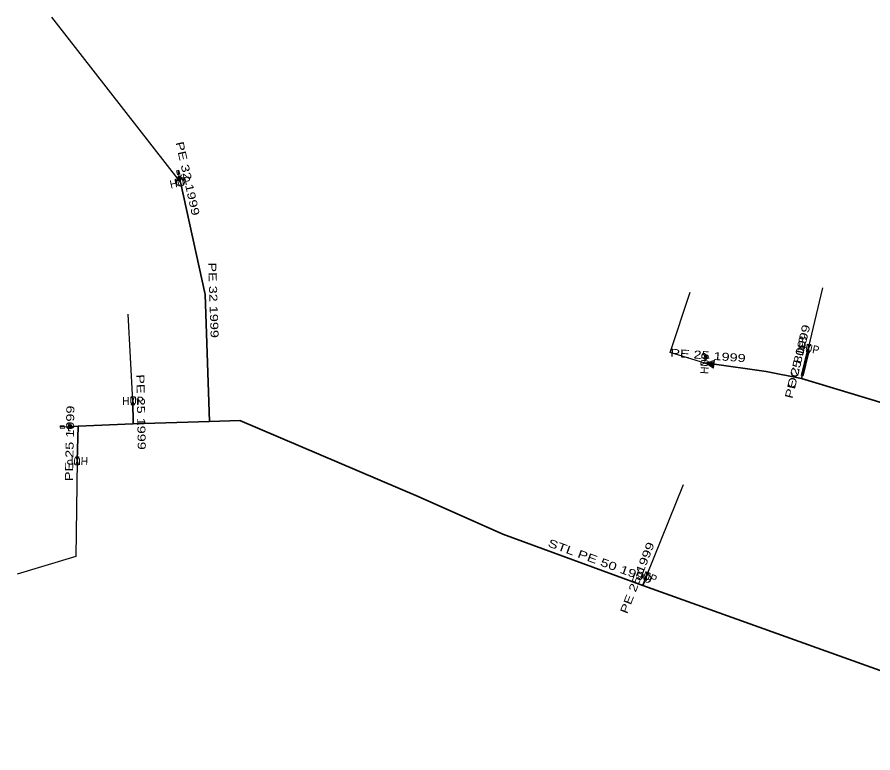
# Model space of a CAD drawing. Extents: x -737484 to -734496, y -1033882 to -1030666.
# Drawn here: x -736088.3 to -735981.3, y -1032114.3 to -1032022.4 of the extents above; entities that cross this region are included whole.
import ezdxf
from ezdxf.enums import TextEntityAlignment as Align

# ---------------------------------------------------------------- set-up
doc = ezdxf.new("R2010")
doc.units = 0
doc.header["$LTSCALE"] = 0.4
for name, color, linetype, lineweight in [('1', 7, 'Continuous', 13), ('18', 7, 'Continuous', 60), ('22', 7, 'Continuous', 25), ('5', 7, 'Continuous', 35), ('7', 7, 'Continuous', 35)]:
    doc.layers.add(name, color=color, linetype=linetype, lineweight=lineweight)
doc.layers.add('2', color=7, linetype='Continuous')

msp = doc.modelspace()

# ---------------------------------------------------------------- linework, layer by layer
at = {"layer": '1'}
for p, q in [((-736068.054, -1032041.921), (-736068.133, -1032041.58)), ((-736067.998, -1032042.499), (-736068.11, -1032042.011)), ((-736067.756, -1032042.062), (-736067.999, -1032042.5)), ((-735989.909, -1032063.546), (-735990.252, -1032063.479)), ((-735989.359, -1032063.73), (-735989.849, -1032063.634)), ((-736002.204, -1032065.043), (-736002.173, -1032064.695)), ((-736002.329, -1032065.61), (-736002.285, -1032065.111)), ((-736081.699, -1032073.034), (-736081.673, -1032073.534)), ((-736082.476, -1032073.501), (-736082.825, -1032073.519)), ((-736081.898, -1032073.546), (-736082.397, -1032073.572))]:
    msp.add_line(p, q, dxfattribs=at)
for points in [[(-736068.222, -1032041.524), (-736068.369, -1032041.558), (-736068.256, -1032042.045), (-736068.11, -1032042.011)], [(-736068.222, -1032041.524), (-736068.076, -1032041.49), (-736067.964, -1032041.978), (-736068.11, -1032042.011)], [(-736068.178, -1032041.553), (-736068.105, -1032041.536), (-736068.009, -1032041.95), (-736068.082, -1032041.967)], [(-736067.888, -1032042.275), (-736067.867, -1032042.287), (-736067.846, -1032042.301), (-736067.827, -1032042.317), (-736067.811, -1032042.335), (-736067.795, -1032042.354), (-736067.782, -1032042.374), (-736067.771, -1032042.396), (-736067.762, -1032042.419), (-736067.755, -1032042.442), (-736067.75, -1032042.467), (-736067.749, -1032042.49), (-736067.749, -1032042.515), (-736067.752, -1032042.54), (-736067.756, -1032042.564), (-736067.765, -1032042.587), (-736067.774, -1032042.61), (-736067.786, -1032042.632), (-736067.8, -1032042.652), (-736067.816, -1032042.671), (-736067.834, -1032042.688), (-736067.853, -1032042.703), (-736067.874, -1032042.716), (-736067.895, -1032042.727), (-736067.918, -1032042.736), (-736067.942, -1032042.744), (-736067.966, -1032042.748), (-736067.991, -1032042.75), (-736068.014, -1032042.749), (-736068.039, -1032042.747), (-736068.063, -1032042.742), (-736068.086, -1032042.734), (-736068.109, -1032042.724), (-736068.13, -1032042.712), (-736068.151, -1032042.698), (-736068.17, -1032042.682), (-736068.186, -1032042.665), (-736068.202, -1032042.645), (-736068.216, -1032042.625), (-736068.226, -1032042.603), (-736068.236, -1032042.581), (-736068.243, -1032042.556), (-736068.247, -1032042.532), (-736068.249, -1032042.508), (-736068.248, -1032042.484), (-736068.246, -1032042.459), (-736068.241, -1032042.435), (-736068.233, -1032042.412), (-736068.223, -1032042.39), (-736068.211, -1032042.368), (-736068.197, -1032042.347), (-736068.181, -1032042.328), (-736068.164, -1032042.312), (-736068.144, -1032042.296), (-736068.124, -1032042.282), (-736068.102, -1032042.272), (-736068.08, -1032042.262), (-736068.056, -1032042.256), (-736068.031, -1032042.251), (-736068.007, -1032042.249), (-736067.983, -1032042.25), (-736067.958, -1032042.253), (-736067.934, -1032042.257), (-736067.911, -1032042.266)], [(-736068.156, -1032042.423), (-736068.148, -1032042.408), (-736068.139, -1032042.393), (-736068.127, -1032042.38), (-736068.114, -1032042.368), (-736068.101, -1032042.357), (-736068.086, -1032042.348), (-736068.071, -1032042.34), (-736068.055, -1032042.334), (-736068.039, -1032042.329), (-736068.022, -1032042.325), (-736068.004, -1032042.325), (-736067.987, -1032042.325), (-736067.97, -1032042.327), (-736067.954, -1032042.33), (-736067.937, -1032042.336), (-736067.922, -1032042.342), (-736067.907, -1032042.35), (-736067.892, -1032042.361), (-736067.879, -1032042.371), (-736067.867, -1032042.384), (-736067.856, -1032042.398), (-736067.847, -1032042.412), (-736067.839, -1032042.427), (-736067.833, -1032042.443), (-736067.828, -1032042.46), (-736067.825, -1032042.477), (-736067.824, -1032042.494), (-736067.824, -1032042.511), (-736067.826, -1032042.528), (-736067.829, -1032042.545), (-736067.835, -1032042.562), (-736067.842, -1032042.577), (-736067.85, -1032042.592), (-736067.86, -1032042.606), (-736067.871, -1032042.62), (-736067.883, -1032042.631), (-736067.897, -1032042.642), (-736067.911, -1032042.651), (-736067.926, -1032042.66), (-736067.942, -1032042.666), (-736067.959, -1032042.67), (-736067.976, -1032042.673), (-736067.993, -1032042.675), (-736068.01, -1032042.675), (-736068.027, -1032042.672), (-736068.044, -1032042.669), (-736068.06, -1032042.663), (-736068.076, -1032042.656), (-736068.091, -1032042.648), (-736068.105, -1032042.638), (-736068.119, -1032042.627), (-736068.13, -1032042.615), (-736068.141, -1032042.602), (-736068.15, -1032042.588), (-736068.159, -1032042.572), (-736068.165, -1032042.556), (-736068.169, -1032042.54), (-736068.173, -1032042.523), (-736068.173, -1032042.505), (-736068.174, -1032042.488), (-736068.171, -1032042.471), (-736068.168, -1032042.455), (-736068.163, -1032042.438)], [(-736067.864, -1032042.566), (-736067.871, -1032042.579), (-736067.88, -1032042.59), (-736067.889, -1032042.603), (-736067.9, -1032042.612), (-736067.911, -1032042.621), (-736067.923, -1032042.629), (-736067.937, -1032042.636), (-736067.95, -1032042.642), (-736067.964, -1032042.646), (-736067.979, -1032042.648), (-736067.994, -1032042.65), (-736068.008, -1032042.649), (-736068.024, -1032042.648), (-736068.038, -1032042.645), (-736068.051, -1032042.64), (-736068.065, -1032042.634), (-736068.078, -1032042.627), (-736068.09, -1032042.619), (-736068.102, -1032042.609), (-736068.112, -1032042.599), (-736068.12, -1032042.587), (-736068.128, -1032042.575), (-736068.136, -1032042.562), (-736068.141, -1032042.548), (-736068.145, -1032042.534), (-736068.148, -1032042.52), (-736068.149, -1032042.504), (-736068.148, -1032042.49), (-736068.147, -1032042.475), (-736068.144, -1032042.461), (-736068.139, -1032042.447), (-736068.134, -1032042.434), (-736068.126, -1032042.421), (-736068.118, -1032042.408), (-736068.109, -1032042.397), (-736068.098, -1032042.387), (-736068.086, -1032042.378), (-736068.074, -1032042.37), (-736068.061, -1032042.363), (-736068.047, -1032042.357), (-736068.033, -1032042.353), (-736068.019, -1032042.351), (-736068.003, -1032042.349), (-736067.989, -1032042.35), (-736067.975, -1032042.351), (-736067.961, -1032042.355), (-736067.946, -1032042.359), (-736067.933, -1032042.364), (-736067.92, -1032042.372), (-736067.908, -1032042.381), (-736067.897, -1032042.39), (-736067.886, -1032042.4), (-736067.877, -1032042.412), (-736067.869, -1032042.424), (-736067.862, -1032042.438), (-736067.856, -1032042.451), (-736067.852, -1032042.465), (-736067.85, -1032042.48), (-736067.848, -1032042.495), (-736067.849, -1032042.509), (-736067.851, -1032042.524), (-736067.853, -1032042.539), (-736067.858, -1032042.552)], [(-736067.931, -1032042.533), (-736067.935, -1032042.539), (-736067.939, -1032042.545), (-736067.943, -1032042.551), (-736067.949, -1032042.555), (-736067.955, -1032042.56), (-736067.961, -1032042.565), (-736067.968, -1032042.568), (-736067.975, -1032042.571), (-736067.982, -1032042.573), (-736067.989, -1032042.575), (-736067.997, -1032042.575), (-736068.003, -1032042.574), (-736068.011, -1032042.574), (-736068.018, -1032042.572), (-736068.025, -1032042.57), (-736068.031, -1032042.567), (-736068.038, -1032042.563), (-736068.044, -1032042.56), (-736068.05, -1032042.555), (-736068.056, -1032042.549), (-736068.059, -1032042.543), (-736068.064, -1032042.537), (-736068.067, -1032042.531), (-736068.07, -1032042.524), (-736068.072, -1032042.517), (-736068.073, -1032042.51), (-736068.074, -1032042.502), (-736068.073, -1032042.495), (-736068.073, -1032042.487), (-736068.071, -1032042.48), (-736068.069, -1032042.473), (-736068.066, -1032042.467), (-736068.063, -1032042.461), (-736068.058, -1032042.454), (-736068.054, -1032042.448), (-736068.048, -1032042.443), (-736068.042, -1032042.439), (-736068.037, -1032042.435), (-736068.029, -1032042.431), (-736068.023, -1032042.429), (-736068.016, -1032042.427), (-736068.009, -1032042.425), (-736068.002, -1032042.425), (-736067.994, -1032042.425), (-736067.987, -1032042.425), (-736067.979, -1032042.427), (-736067.972, -1032042.429), (-736067.966, -1032042.432), (-736067.959, -1032042.436), (-736067.953, -1032042.44), (-736067.947, -1032042.444), (-736067.942, -1032042.45), (-736067.938, -1032042.456), (-736067.934, -1032042.462), (-736067.93, -1032042.469), (-736067.928, -1032042.476), (-736067.926, -1032042.482), (-736067.924, -1032042.489), (-736067.924, -1032042.497), (-736067.924, -1032042.504), (-736067.925, -1032042.512), (-736067.926, -1032042.519), (-736067.928, -1032042.526)], [(-735990.34, -1032063.539), (-735990.369, -1032063.686), (-735989.878, -1032063.781), (-735989.849, -1032063.634)], [(-735990.34, -1032063.539), (-735990.312, -1032063.391), (-735989.821, -1032063.487), (-735989.849, -1032063.634)], [(-735990.296, -1032063.51), (-735990.281, -1032063.436), (-735989.864, -1032063.517), (-735989.879, -1032063.591)], [(-735989.46, -1032063.207), (-735989.068, -1032063.283), (-735989.651, -1032064.188), (-735989.259, -1032064.264)], [(-736002.241, -1032064.613), (-736002.391, -1032064.6), (-736002.434, -1032065.098), (-736002.285, -1032065.111)], [(-736002.241, -1032064.613), (-736002.092, -1032064.626), (-736002.135, -1032065.124), (-736002.285, -1032065.111)], [(-736002.208, -1032064.654), (-736002.133, -1032064.661), (-736002.17, -1032065.084), (-736002.245, -1032065.078)], [(-736002.842, -1032065.773), (-736002.814, -1032065.374), (-736001.845, -1032065.843), (-736001.817, -1032065.444)], [(-736001.273, -1032066.22), (-736001.134, -1032065.23), (-736002.194, -1032065.586)], [(-736001.255, -1032065.376), (-736001.972, -1032065.617), (-736001.349, -1032066.046)], [(-736001.751, -1032065.648), (-736001.426, -1032065.872), (-736001.377, -1032065.522)], [(-736074.036, -1032069.802), (-736073.636, -1032069.795), (-736074.019, -1032070.802), (-736073.619, -1032070.795)], [(-736082.896, -1032073.598), (-736082.904, -1032073.448), (-736082.405, -1032073.422), (-736082.397, -1032073.572)], [(-736082.896, -1032073.598), (-736082.888, -1032073.748), (-736082.389, -1032073.721), (-736082.397, -1032073.572)], [(-736082.86, -1032073.559), (-736082.864, -1032073.484), (-736082.44, -1032073.462), (-736082.436, -1032073.537)], [(-736081.698, -1032073.284), (-736081.674, -1032073.283), (-736081.648, -1032073.285), (-736081.624, -1032073.288), (-736081.601, -1032073.294), (-736081.577, -1032073.302), (-736081.556, -1032073.312), (-736081.534, -1032073.325), (-736081.514, -1032073.34), (-736081.497, -1032073.356), (-736081.48, -1032073.374), (-736081.466, -1032073.393), (-736081.452, -1032073.415), (-736081.442, -1032073.437), (-736081.433, -1032073.46), (-736081.428, -1032073.484), (-736081.423, -1032073.508), (-736081.422, -1032073.533), (-736081.424, -1032073.558), (-736081.427, -1032073.582), (-736081.433, -1032073.606), (-736081.441, -1032073.629), (-736081.452, -1032073.651), (-736081.464, -1032073.672), (-736081.479, -1032073.692), (-736081.495, -1032073.71), (-736081.513, -1032073.726), (-736081.533, -1032073.742), (-736081.554, -1032073.754), (-736081.576, -1032073.765), (-736081.599, -1032073.773), (-736081.623, -1032073.779), (-736081.647, -1032073.783), (-736081.671, -1032073.784), (-736081.696, -1032073.783), (-736081.721, -1032073.779), (-736081.744, -1032073.774), (-736081.768, -1032073.765), (-736081.79, -1032073.755), (-736081.811, -1032073.742), (-736081.831, -1032073.728), (-736081.849, -1032073.711), (-736081.865, -1032073.693), (-736081.88, -1032073.674), (-736081.893, -1032073.652), (-736081.904, -1032073.631), (-736081.912, -1032073.607), (-736081.918, -1032073.583), (-736081.921, -1032073.56), (-736081.923, -1032073.535), (-736081.922, -1032073.51), (-736081.918, -1032073.485), (-736081.913, -1032073.462), (-736081.904, -1032073.438), (-736081.894, -1032073.416), (-736081.881, -1032073.395), (-736081.867, -1032073.375), (-736081.85, -1032073.358), (-736081.832, -1032073.341), (-736081.813, -1032073.326), (-736081.791, -1032073.313), (-736081.769, -1032073.303), (-736081.746, -1032073.294), (-736081.722, -1032073.289)], [(-736081.847, -1032073.552), (-736081.848, -1032073.535), (-736081.848, -1032073.518), (-736081.844, -1032073.5), (-736081.84, -1032073.483), (-736081.835, -1032073.467), (-736081.827, -1032073.451), (-736081.819, -1032073.437), (-736081.808, -1032073.423), (-736081.797, -1032073.41), (-736081.785, -1032073.398), (-736081.77, -1032073.388), (-736081.756, -1032073.38), (-736081.74, -1032073.372), (-736081.724, -1032073.366), (-736081.708, -1032073.362), (-736081.691, -1032073.359), (-736081.674, -1032073.358), (-736081.656, -1032073.359), (-736081.639, -1032073.362), (-736081.622, -1032073.366), (-736081.606, -1032073.372), (-736081.59, -1032073.379), (-736081.576, -1032073.387), (-736081.562, -1032073.398), (-736081.549, -1032073.41), (-736081.537, -1032073.422), (-736081.527, -1032073.436), (-736081.519, -1032073.45), (-736081.511, -1032073.466), (-736081.505, -1032073.483), (-736081.501, -1032073.499), (-736081.498, -1032073.516), (-736081.497, -1032073.533), (-736081.498, -1032073.55), (-736081.5, -1032073.568), (-736081.505, -1032073.584), (-736081.511, -1032073.6), (-736081.518, -1032073.616), (-736081.526, -1032073.631), (-736081.537, -1032073.645), (-736081.549, -1032073.657), (-736081.561, -1032073.669), (-736081.575, -1032073.68), (-736081.589, -1032073.688), (-736081.605, -1032073.695), (-736081.622, -1032073.701), (-736081.637, -1032073.705), (-736081.655, -1032073.708), (-736081.672, -1032073.709), (-736081.689, -1032073.708), (-736081.707, -1032073.706), (-736081.723, -1032073.701), (-736081.739, -1032073.696), (-736081.754, -1032073.689), (-736081.77, -1032073.68), (-736081.784, -1032073.669), (-736081.796, -1032073.658), (-736081.808, -1032073.646), (-736081.818, -1032073.631), (-736081.827, -1032073.617), (-736081.834, -1032073.601), (-736081.84, -1032073.585), (-736081.845, -1032073.569)], [(-736081.523, -1032073.519), (-736081.522, -1032073.534), (-736081.524, -1032073.548), (-736081.525, -1032073.563), (-736081.529, -1032073.577), (-736081.533, -1032073.59), (-736081.54, -1032073.604), (-736081.548, -1032073.617), (-736081.556, -1032073.629), (-736081.566, -1032073.639), (-736081.577, -1032073.65), (-736081.589, -1032073.658), (-736081.601, -1032073.666), (-736081.615, -1032073.673), (-736081.629, -1032073.677), (-736081.643, -1032073.681), (-736081.658, -1032073.683), (-736081.673, -1032073.684), (-736081.687, -1032073.683), (-736081.702, -1032073.681), (-736081.716, -1032073.678), (-736081.729, -1032073.673), (-736081.743, -1032073.666), (-736081.756, -1032073.659), (-736081.768, -1032073.65), (-736081.779, -1032073.64), (-736081.789, -1032073.63), (-736081.797, -1032073.617), (-736081.805, -1032073.605), (-736081.812, -1032073.592), (-736081.816, -1032073.578), (-736081.82, -1032073.563), (-736081.822, -1032073.549), (-736081.823, -1032073.534), (-736081.822, -1032073.519), (-736081.82, -1032073.505), (-736081.817, -1032073.491), (-736081.812, -1032073.477), (-736081.805, -1032073.463), (-736081.798, -1032073.451), (-736081.79, -1032073.439), (-736081.779, -1032073.428), (-736081.769, -1032073.418), (-736081.756, -1032073.409), (-736081.744, -1032073.401), (-736081.731, -1032073.395), (-736081.717, -1032073.391), (-736081.702, -1032073.387), (-736081.688, -1032073.384), (-736081.673, -1032073.383), (-736081.658, -1032073.385), (-736081.644, -1032073.387), (-736081.63, -1032073.39), (-736081.616, -1032073.394), (-736081.602, -1032073.401), (-736081.59, -1032073.409), (-736081.577, -1032073.417), (-736081.567, -1032073.427), (-736081.557, -1032073.438), (-736081.548, -1032073.45), (-736081.54, -1032073.462), (-736081.534, -1032073.476), (-736081.529, -1032073.49), (-736081.526, -1032073.504)], [(-736081.598, -1032073.527), (-736081.597, -1032073.534), (-736081.598, -1032073.541), (-736081.599, -1032073.548), (-736081.601, -1032073.555), (-736081.603, -1032073.562), (-736081.607, -1032073.569), (-736081.61, -1032073.575), (-736081.615, -1032073.582), (-736081.62, -1032073.587), (-736081.624, -1032073.592), (-736081.631, -1032073.596), (-736081.637, -1032073.6), (-736081.644, -1032073.603), (-736081.651, -1032073.605), (-736081.658, -1032073.608), (-736081.665, -1032073.608), (-736081.673, -1032073.609), (-736081.68, -1032073.609), (-736081.687, -1032073.607), (-736081.695, -1032073.606), (-736081.701, -1032073.603), (-736081.708, -1032073.6), (-736081.714, -1032073.597), (-736081.72, -1032073.592), (-736081.726, -1032073.587), (-736081.73, -1032073.582), (-736081.735, -1032073.576), (-736081.739, -1032073.569), (-736081.742, -1032073.562), (-736081.744, -1032073.555), (-736081.746, -1032073.548), (-736081.747, -1032073.541), (-736081.748, -1032073.534), (-736081.747, -1032073.526), (-736081.746, -1032073.519), (-736081.745, -1032073.512), (-736081.742, -1032073.505), (-736081.739, -1032073.499), (-736081.735, -1032073.492), (-736081.731, -1032073.486), (-736081.726, -1032073.481), (-736081.721, -1032073.476), (-736081.715, -1032073.472), (-736081.708, -1032073.467), (-736081.702, -1032073.464), (-736081.694, -1032073.462), (-736081.687, -1032073.46), (-736081.68, -1032073.459), (-736081.672, -1032073.458), (-736081.665, -1032073.459), (-736081.658, -1032073.46), (-736081.651, -1032073.461), (-736081.644, -1032073.464), (-736081.638, -1032073.468), (-736081.631, -1032073.471), (-736081.625, -1032073.476), (-736081.62, -1032073.481), (-736081.615, -1032073.485), (-736081.611, -1032073.492), (-736081.606, -1032073.498), (-736081.604, -1032073.505), (-736081.601, -1032073.512), (-736081.599, -1032073.519)], [(-736080.577, -1032078.302), (-736080.977, -1032078.295), (-736080.56, -1032077.302), (-736080.96, -1032077.295)], [(-736009.635, -1032091.66), (-736009.262, -1032091.803), (-736009.993, -1032092.594), (-736009.62, -1032092.737)]]:
    msp.add_lwpolyline(points, close=True, dxfattribs=at)
for points in [[(-736068.429, -1032042.855), (-736068.486, -1032042.611), (-736067.511, -1032042.386), (-736067.455, -1032042.63)], [(-736081.622, -1032074.035), (-736081.871, -1032074.048), (-736081.924, -1032073.049), (-736081.674, -1032073.036)]]:
    msp.add_lwpolyline(points, dxfattribs=at)
msp.add_circle((-736067.8895, -1032042.9904), 0.5, dxfattribs=at)
at = {"layer": '18'}
msp.add_line((-735990.159, -1032067.17), (-735989.446, -1032064.254), dxfattribs=at)
at = {"layer": '22'}
for p, q in [((-736067.889, -1032042.99), (-736083.949, -1032022.354)), ((-735989.36, -1032063.736), (-735987.578, -1032056.176)), ((-736073.829, -1032070.3), (-736074.413, -1032059.495)), ((-736009.629, -1032092.199), (-736004.985, -1032080.775))]:
    msp.add_line(p, q, dxfattribs=at)
for points in [[(-736002.33, -1032065.609), (-736006.688, -1032064.262), (-736004.182, -1032056.74)], [(-736080.769, -1032077.799), (-736080.96, -1032089.741), (-736088.292, -1032091.967)]]:
    msp.add_lwpolyline(points, dxfattribs=at)
at = {"layer": '5'}
for points in [[(-735934.539, -1032083.49), (-735935.07, -1032083.29), (-735935.27, -1032083.21), (-735951.29, -1032078.52), (-735951.55, -1032078.45), (-735951.78, -1032078.38), (-735967.28, -1032074.44), (-735967.42, -1032074.41), (-735967.64, -1032074.36), (-735990.24, -1032067.51), (-735994.68, -1032066.65), (-736001.699, -1032065.656)], [(-735949.816, -1032114.299), (-735976, -1032105.59), (-736010.09, -1032093.38), (-736027.57, -1032086.98), (-736038.17, -1032082.27), (-736060.44, -1032072.76), (-736064.24, -1032072.87), (-736073.77, -1032073.16), (-736080.68, -1032073.48), (-736081.898, -1032073.549)]]:
    msp.add_lwpolyline(points, dxfattribs=at)
at = {"layer": '7'}
for p, q in [((-736067.889, -1032042.99), (-736067.999, -1032042.499)), ((-736001.699, -1032065.656), (-736002.33, -1032065.609)), ((-736073.77, -1032073.16), (-736073.828, -1032070.299)), ((-736080.68, -1032073.48), (-736080.769, -1032077.799)), ((-736010.09, -1032093.38), (-736009.628, -1032092.199))]:
    msp.add_line(p, q, dxfattribs=at)
for points in [[(-736064.24, -1032072.87), (-736064.78, -1032057.02), (-736067.889, -1032042.99)], [(-735990.24, -1032067.51), (-735990.16, -1032067.17), (-735989.51, -1032064.51), (-735989.46, -1032064.26), (-735989.36, -1032063.736)]]:
    msp.add_lwpolyline(points, dxfattribs=at)

# ---------------------------------------------------------------- texts
at = {"layer": '18', "width": 1.35}
msp.add_text('OC 80 3', height=1, rotation=76.26, dxfattribs=at).set_placement((-735990.2876, -1032065.5928), align=Align.CENTER)
at = {"layer": '2', "width": 0.95}
for rotation, p in [(13, (-736067.776, -1032043.4765)), (349, (-735989.4549, -1032064.2261)), (86, (-736001.8304, -1032065.6434)), (1, (-736073.8182, -1032070.7988)), (179, (-736080.7598, -1032077.2988)), (339, (-736009.8067, -1032092.6653))]:
    msp.add_text('HUP', height=1, rotation=rotation, dxfattribs=at).set_placement(p, align=Align.CENTER)
at = {"layer": '5', "width": 1.4}
msp.add_text('STL PE 50 1999', height=1, rotation=339.891, dxfattribs=at).set_placement((-736015.5974, -1032090.8301), align=Align.CENTER)
at = {"layer": '7', "width": 1.35}
for s, rotation, p in [('PE 32 1999', 282.628, (-736067.4558, -1032042.6352)), ('PE 32 1999', 271.951, (-736064.2546, -1032057.7465)), ('PE 25 1999', 76.268, (-735990.2678, -1032065.5072)), ('PE 25 1999', 355.74, (-736001.9771, -1032065.1335)), ('PE 25 1999', 271.161, (-736073.2987, -1032071.7189)), ('PE 25 1999', 88.819, (-736081.2241, -1032075.6288)), ('PE 25 1999', 68.635, (-736010.3236, -1032092.6067))]:
    msp.add_text(s, height=1, rotation=rotation, dxfattribs=at).set_placement(p, align=Align.CENTER)

doc.saveas('drawing.dxf')
